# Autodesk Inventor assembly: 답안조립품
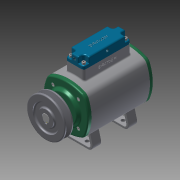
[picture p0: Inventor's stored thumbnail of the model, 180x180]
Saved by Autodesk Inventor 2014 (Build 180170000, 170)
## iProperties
Created: 2016-10
Part Number: 답안조립품
Document SubType Name: Assembly
Designer: 703-16
Mass: 2460.38 g
Surface Area: 2685.98 cm^2
Volume: 916.99 cm^3
Density: 2.6831 g/cm^3
Author: 703-16
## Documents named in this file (18)
- C:\Users\703-16\Desktop\361008V1025\답안조립품.iam
- C:\Users\703-16\Desktop\361008V1025\본체.ipt
- C:\Users\703-16\Desktop\361008V1025\V-벨트풀리.ipt
- C:\Users\703-16\Desktop\361008V1025\뒷커버.ipt
- C:\Users\703-16\Desktop\361008V1025\멈춤나사 M4x5.ipt
- C:\Users\703-16\Desktop\361008V1025\베어링 6203.ipt
- C:\Users\703-16\Desktop\361008V1025\볼트 M4 x 12.ipt
- C:\Users\703-16\Desktop\361008V1025\볼트 M4 x 16.ipt
- C:\Users\703-16\Desktop\361008V1025\부시.ipt
- C:\Users\703-16\Desktop\361008V1025\스프링1.ipt
- C:\Users\703-16\Desktop\361008V1025\스프링2.ipt
- C:\Users\703-16\Desktop\361008V1025\스프링3.ipt
- C:\Users\703-16\Desktop\361008V1025\슬라이드.ipt
- C:\Users\703-16\Desktop\361008V1025\앞커버.ipt
- C:\Users\703-16\Desktop\361008V1025\오일실 17 30 8.ipt
- C:\Users\703-16\Desktop\361008V1025\축.ipt
- C:\Users\703-16\Desktop\361008V1025\키 - 5 x 5 x 18.ipt
- C:\Users\703-16\Desktop\361008V1025\헤더커버.ipt
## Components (4 placed, 3 different names)
1. V-벨트풀리:1 — 플러쉬:1
2. 7-베어링 6203:1
3. 헤더커버:1 — 각도:1, 각도:2
4. 7-베어링 6203:2
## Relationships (3: Angle 2, Flush 1)
- 플러쉬:1 [Flush]: V-벨트풀리:1
- 각도:1 [Angle]: 헤더커버:1
- 각도:2 [Angle]: 헤더커버:1
